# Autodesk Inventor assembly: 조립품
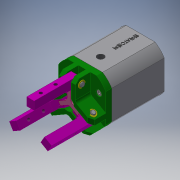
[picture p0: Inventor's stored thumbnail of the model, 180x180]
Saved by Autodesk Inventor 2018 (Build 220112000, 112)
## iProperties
Created: 2020-02
Part Number: 조립품
Material: 일반
Document SubType Name: Assembly
Designer: USER
Author: USER
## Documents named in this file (13)
- C:\Users\USER\Desktop\700206V1030\조립품.iam
- C:\Users\USER\Desktop\700206V1030\본체.ipt
- C:\Users\USER\Desktop\700206V1030\E링.ipt
- C:\Users\USER\Desktop\700206V1030\O-RING 12x16.ipt
- C:\Users\USER\Desktop\700206V1030\O-RING 18x22.ipt
- C:\Users\USER\Desktop\700206V1030\O-RING 34x40.ipt
- C:\Users\USER\Desktop\700206V1030\로드.ipt
- C:\Users\USER\Desktop\700206V1030\본체헤드.ipt
- C:\Users\USER\Desktop\700206V1030\볼트 M4.ipt
- C:\Users\USER\Desktop\700206V1030\피스톤.ipt
- C:\Users\USER\Desktop\700206V1030\핀 A.ipt
- C:\Users\USER\Desktop\700206V1030\핀 B.ipt
- C:\Users\USER\Desktop\700206V1030\핑거.ipt
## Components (20 placed, 8 different names)
1. E링:1
2. O-RING 12x16:1
3. O-RING 18x22:1
4. O-RING 34x40:1
5. 피스톤:1
6. 핀 A:1
7. 핀 B:1
8. 핑거:1
9. O-RING 34x40:2
10. 핀 B:2
11. 핀 B:3
12. 핑거:2
13. 핑거:3
14. 핀 A:2
15. 핀 A:3
16. E링:2
17. E링:3
18. E링:4
19. E링:5
20. E링:6
